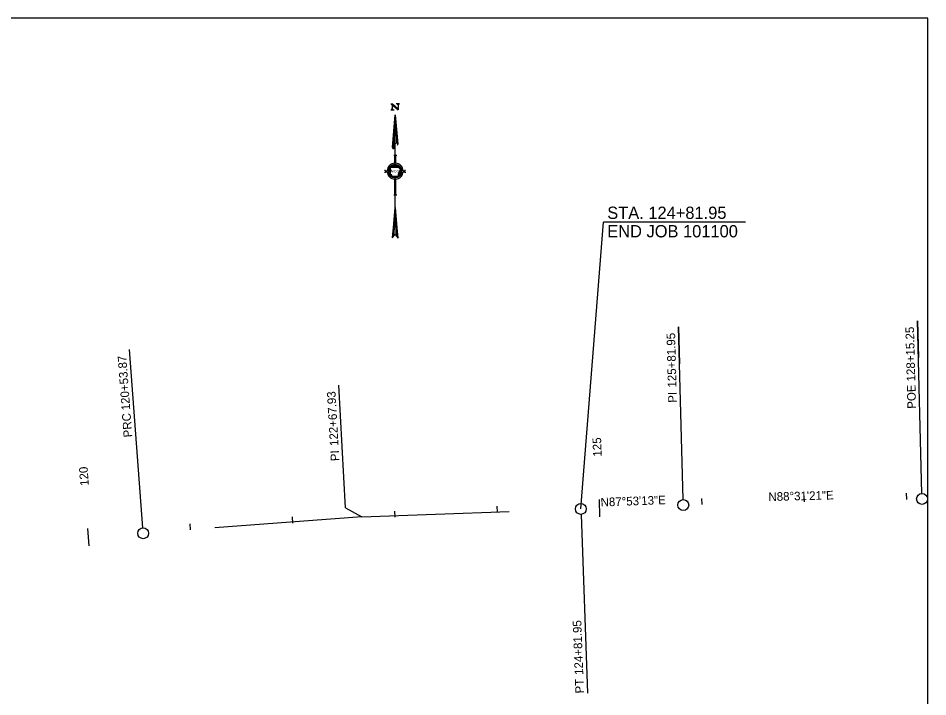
# Model space of a CAD drawing. Extents: x 1806834 to 1810084, y 678065 to 679314.
# Drawn here: x 1809196 to 1810084, y 678402 to 679065 of the extents above; entities that cross this region are included whole.
import ezdxf

# ---------------------------------------------------------------- set-up
doc = ezdxf.new("R2010")
doc.units = 0
for name, color, linetype in [('_PROJECT LIMITS', 7, 'Continuous'), ('Default', 7, 'Continuous'), ('DSN_DRFT_Guideline-No-Plot', 7, 'Continuous'), ('DSN_RDWY_Alignment Annotation', 7, 'Continuous')]:
    doc.layers.add(name, color=color, linetype=linetype)

msp = doc.modelspace()

# ---------------------------------------------------------------- linework, layer by layer
at = {"layer": '_PROJECT LIMITS'}
for p in [(1809745.12, 678585.51), (1809905.96, 678865.52)]:
    msp.add_line(p, (1809767.17, 678865.52), dxfattribs=at)
at = {"layer": 'Default'}
for p, q in [((1809559.44, 678980.98), (1809561.21, 678980.98)), ((1809559.98, 678980.98), (1809566.66, 678975.04)), ((1809560.06, 678980.98), (1809566.66, 678975.12)), ((1809560.13, 678980.98), (1809566.66, 678975.17)), ((1809560.21, 678980.98), (1809566.66, 678975.25)), ((1809560.29, 678980.98), (1809566.66, 678975.3)), ((1809560.37, 678980.98), (1809566.66, 678975.38)), ((1809560.42, 678980.98), (1809566.66, 678975.43)), ((1809560.49, 678980.98), (1809566.66, 678975.5)), ((1809560.57, 678980.98), (1809566.66, 678975.56)), ((1809560.65, 678980.98), (1809566.66, 678975.63)), ((1809560.73, 678980.98), (1809566.66, 678975.71)), ((1809560.8, 678980.98), (1809566.66, 678975.76)), ((1809560.83, 678980.98), (1809560.83, 678975.04)), ((1809560.88, 678980.98), (1809566.66, 678975.84)), ((1809560.93, 678980.98), (1809566.66, 678975.89)), ((1809561.01, 678980.98), (1809566.66, 678975.97)), ((1809561.09, 678980.98), (1809566.66, 678976.02)), ((1809561.16, 678980.98), (1809566.66, 678976.1)), ((1809561.21, 678980.98), (1809566.66, 678976.12)), ((1809566.27, 678980.98), (1809564.78, 678980.98)), ((1809568.02, 678980.98), (1809566.27, 678980.98)), ((1809566.66, 678980.98), (1809566.66, 678975.04)), ((1809559.44, 678975.04), (1809561.21, 678975.04)), ((1809561.21, 678975.04), (1809562.7, 678975.04)), ((1809563.83, 678921.99), (1809563.83, 678941.93)), ((1809561.44, 678937.53), (1809561.44, 678938.3)), ((1809561.83, 678937.22), (1809561.83, 678939.07)), ((1809562.19, 678937.15), (1809562.19, 678939.61)), ((1809562.65, 678937.15), (1809562.65, 678940.77)), ((1809562.37, 678930.7), (1809563.35, 678930.7)), ((1809563.35, 678922.94), (1809563.35, 678930.7)), ((1809564.32, 678922.97), (1809564.32, 678930.7)), ((1809564.32, 678930.7), (1809565.3, 678930.7)), ((1809554.1, 678915.67), (1809554.1, 678916.65)), ((1809554.1, 678915.67), (1809556.06, 678915.67)), ((1809554.1, 678913.72), (1809554.1, 678914.69)), ((1809554.1, 678914.69), (1809556.06, 678914.69)), ((1809557.26, 678913.54), (1809557.26, 678916.77)), ((1809557.49, 678912.77), (1809557.49, 678917.52)), ((1809557.75, 678912.25), (1809557.75, 678918.08)), ((1809557.98, 678911.84), (1809557.98, 678918.52)), ((1809558.23, 678911.46), (1809558.23, 678918.91)), ((1809558.46, 678911.1), (1809558.46, 678919.29)), ((1809558.72, 678910.86), (1809558.72, 678919.6)), ((1809558.95, 678910.58), (1809558.95, 678919.83)), ((1809559.49, 678916.18), (1809559.03, 678919.16)), ((1809559.03, 678919.16), (1809567.92, 678919.16)), ((1809559.21, 678919.16), (1809559.21, 678920.09)), ((1809559.21, 678910.33), (1809559.21, 678917.93)), ((1809559.29, 678911.69), (1809559.49, 678916.18)), ((1809559.44, 678919.16), (1809559.44, 678920.29)), ((1809559.44, 678915.64), (1809559.44, 678916.31)), ((1809559.7, 678919.16), (1809559.7, 678920.52)), ((1809559.93, 678919.16), (1809559.93, 678920.7)), ((1809560.19, 678919.16), (1809560.19, 678920.86)), ((1809560.42, 678919.16), (1809560.42, 678921.01)), ((1809560.67, 678919.16), (1809560.67, 678921.14)), ((1809560.91, 678919.16), (1809560.91, 678921.27)), ((1809561.16, 678919.16), (1809561.16, 678921.37)), ((1809561.39, 678919.16), (1809561.39, 678921.48)), ((1809561.62, 678919.16), (1809561.62, 678921.58)), ((1809561.88, 678919.16), (1809561.88, 678921.65)), ((1809562.11, 678919.16), (1809562.11, 678921.73)), ((1809562.37, 678919.16), (1809562.37, 678921.78)), ((1809562.6, 678919.16), (1809562.6, 678921.84)), ((1809562.86, 678919.16), (1809562.86, 678921.86)), ((1809563.09, 678919.16), (1809563.09, 678921.91)), ((1809563.35, 678919.16), (1809563.35, 678921.94)), ((1809563.58, 678919.16), (1809563.58, 678921.96)), ((1809563.83, 678919.16), (1809563.83, 678921.99)), ((1809564.07, 678919.16), (1809564.07, 678921.94)), ((1809564.32, 678919.16), (1809564.32, 678921.94)), ((1809564.55, 678919.16), (1809564.55, 678921.89)), ((1809564.81, 678919.16), (1809564.81, 678921.86)), ((1809565.04, 678919.16), (1809565.04, 678921.81)), ((1809565.3, 678919.16), (1809565.3, 678921.76)), ((1809565.53, 678919.16), (1809565.53, 678921.71)), ((1809565.76, 678919.16), (1809565.76, 678921.63)), ((1809566.02, 678919.16), (1809566.02, 678921.55)), ((1809566.25, 678919.16), (1809566.25, 678921.48)), ((1809566.51, 678919.16), (1809566.51, 678921.37)), ((1809566.74, 678919.16), (1809566.74, 678921.27)), ((1809566.99, 678919.16), (1809566.99, 678921.14)), ((1809567.23, 678919.16), (1809567.23, 678921.01)), ((1809567.48, 678919.16), (1809567.48, 678920.86)), ((1809567.87, 678914.36), (1809567.53, 678913.67)), ((1809567.71, 678919.16), (1809567.71, 678920.68)), ((1809568.07, 678918.37), (1809567.74, 678917.67)), ((1809567.74, 678917.67), (1809569.25, 678917.67)), ((1809568.38, 678915.1), (1809567.87, 678914.36)), ((1809567.92, 678919.16), (1809567.92, 678919.16)), ((1809567.92, 678919.16), (1809568.12, 678918.8)), ((1809567.97, 678919.11), (1809567.97, 678920.52)), ((1809567.97, 678917.67), (1809567.97, 678918.11)), ((1809567.97, 678909.84), (1809567.97, 678914.44)), ((1809568.12, 678918.8), (1809568.07, 678918.37)), ((1809568.2, 678917.7), (1809568.2, 678920.29)), ((1809568.2, 678910.04), (1809568.2, 678914.8)), ((1809568.66, 678915.9), (1809568.38, 678915.1)), ((1809568.46, 678917.7), (1809568.46, 678920.11)), ((1809568.46, 678910.25), (1809568.46, 678915.28)), ((1809568.66, 678915.9), (1809568.92, 678916.54)), ((1809568.69, 678917.7), (1809568.69, 678919.86)), ((1809568.69, 678910.5), (1809568.69, 678915.93)), ((1809569.36, 678917.08), (1809568.92, 678916.54)), ((1809568.95, 678917.67), (1809568.95, 678919.6)), ((1809568.95, 678910.76), (1809568.95, 678916.54)), ((1809569.18, 678917.67), (1809569.18, 678919.34)), ((1809569.18, 678911.07), (1809569.18, 678916.85)), ((1809569.25, 678917.67), (1809569.46, 678917.42)), ((1809569.46, 678917.42), (1809569.36, 678917.08)), ((1809569.44, 678917.49), (1809569.44, 678918.98)), ((1809569.44, 678911.4), (1809569.44, 678917.24)), ((1809569.67, 678911.76), (1809569.67, 678918.57)), ((1809569.9, 678912.23), (1809569.9, 678918.14)), ((1809570.15, 678912.79), (1809570.15, 678917.57)), ((1809570.39, 678913.61), (1809570.39, 678916.8)), ((1809571.6, 678915.67), (1809573.55, 678915.67)), ((1809571.6, 678914.69), (1809573.55, 678914.69)), ((1809573.55, 678915.67), (1809573.55, 678916.65)), ((1809573.55, 678914.69), (1809573.55, 678913.72)), ((1809559.67, 678911.46), (1809559.29, 678911.69)), ((1809559.44, 678910.12), (1809559.44, 678911.56)), ((1809560.42, 678911.46), (1809559.67, 678911.46)), ((1809559.7, 678909.91), (1809559.7, 678911.43)), ((1809559.93, 678909.71), (1809559.93, 678911.43)), ((1809560.19, 678909.58), (1809560.19, 678911.43)), ((1809560.42, 678909.86), (1809560.42, 678911.46)), ((1809566.63, 678909.86), (1809560.42, 678909.86)), ((1809560.42, 678909.4), (1809560.42, 678909.84)), ((1809560.67, 678909.27), (1809560.67, 678909.86)), ((1809560.91, 678909.14), (1809560.91, 678909.86)), ((1809561.16, 678909.04), (1809561.16, 678909.86)), ((1809561.39, 678908.94), (1809561.39, 678909.86)), ((1809561.62, 678908.84), (1809561.62, 678909.86)), ((1809561.88, 678908.76), (1809561.88, 678909.86)), ((1809562.11, 678908.68), (1809562.11, 678909.86)), ((1809562.37, 678908.63), (1809562.37, 678909.86)), ((1809562.6, 678908.55), (1809562.6, 678909.86)), ((1809562.86, 678908.53), (1809562.86, 678909.86)), ((1809563.09, 678908.5), (1809563.09, 678909.86)), ((1809563.35, 678908.45), (1809563.35, 678909.86)), ((1809563.35, 678892.14), (1809563.35, 678907.42)), ((1809563.58, 678908.42), (1809563.58, 678909.86)), ((1809563.83, 678908.42), (1809563.83, 678909.86)), ((1809563.83, 678879.67), (1809563.83, 678908.37)), ((1809564.07, 678908.42), (1809564.07, 678909.86)), ((1809564.32, 678908.45), (1809564.32, 678909.86)), ((1809564.32, 678892.14), (1809564.32, 678907.42)), ((1809564.55, 678908.48), (1809564.55, 678909.86)), ((1809564.81, 678908.5), (1809564.81, 678909.86)), ((1809565.04, 678908.55), (1809565.04, 678909.86)), ((1809565.3, 678908.6), (1809565.3, 678909.86)), ((1809565.53, 678908.66), (1809565.53, 678909.86)), ((1809565.76, 678908.73), (1809565.76, 678909.86)), ((1809566.02, 678908.78), (1809566.02, 678909.86)), ((1809566.25, 678908.89), (1809566.25, 678909.86)), ((1809566.51, 678908.99), (1809566.51, 678909.86)), ((1809566.94, 678910.5), (1809566.63, 678909.86)), ((1809566.74, 678909.09), (1809566.74, 678909.99)), ((1809566.99, 678912.74), (1809566.84, 678911.56)), ((1809566.84, 678911.56), (1809566.94, 678910.5)), ((1809567.53, 678913.67), (1809566.99, 678912.74)), ((1809566.99, 678909.22), (1809566.99, 678912.53)), ((1809567.23, 678909.35), (1809567.23, 678913.05)), ((1809567.48, 678909.5), (1809567.48, 678913.49)), ((1809567.71, 678909.66), (1809567.71, 678913.97)), ((1809562.37, 678892.14), (1809563.35, 678892.14)), ((1809564.32, 678892.14), (1809565.3, 678892.14)), ((1809563.83, 678879.67), (1809560.77, 678850.16)), ((1809566.8, 678849.93), (1809563.83, 678879.67)), ((1809560.77, 678850.16), (1809563.83, 678853.21)), ((1809563.83, 678853.21), (1809566.8, 678849.93))]:
    msp.add_line(p, q, dxfattribs=at)
for points in [[(1809567.48, 678980.98), (1809566.66, 678979.95), (1809565.86, 678980.98), (1809565.99, 678980.93), (1809567.38, 678980.93), (1809566.66, 678980.03), (1809566.02, 678980.87), (1809567.3, 678980.9), (1809566.66, 678980.13), (1809566.12, 678980.82), (1809567.17, 678980.85), (1809566.66, 678980.21), (1809566.22, 678980.77), (1809567.05, 678980.8), (1809566.66, 678980.31), (1809566.35, 678980.72), (1809566.94, 678980.75), (1809566.66, 678980.39), (1809566.45, 678980.67), (1809566.81, 678980.69), (1809566.66, 678980.46), (1809566.56, 678980.64), (1809566.71, 678980.64), (1809566.66, 678980.54), (1809566.63, 678980.62), (1809566.66, 678980.62)], [(1809559.98, 678975.04), (1809560.83, 678976.07), (1809561.6, 678975.04), (1809561.5, 678975.09), (1809560.08, 678975.09), (1809560.8, 678975.99), (1809561.47, 678975.14), (1809560.19, 678975.12), (1809560.8, 678975.89), (1809561.37, 678975.2), (1809560.29, 678975.17), (1809560.8, 678975.81), (1809561.24, 678975.25), (1809560.44, 678975.22), (1809560.83, 678975.74), (1809561.11, 678975.3), (1809560.55, 678975.27), (1809560.8, 678975.63), (1809561.01, 678975.35), (1809560.65, 678975.32), (1809560.8, 678975.56), (1809560.91, 678975.38), (1809560.75, 678975.38), (1809560.8, 678975.48), (1809560.85, 678975.4), (1809560.83, 678975.4)], [(1809561.27, 678938.15), (1809563.83, 678970.16), (1809566.4, 678941.64)], [(1809561.88, 678940.59), (1809563.83, 678970.16), (1809565.89, 678942.9)], [(1809562.42, 678941.28), (1809563.83, 678970.16), (1809565.2, 678943.06)], [(1809563.22, 678942.13), (1809563.83, 678970.16), (1809564.42, 678942.98)], [(1809561.57, 678851.99), (1809563.83, 678879.67), (1809565.99, 678851.9)], [(1809565.31, 678852.66), (1809563.83, 678879.67), (1809562.26, 678852.67)], [(1809562.94, 678853.33), (1809563.83, 678879.67), (1809564.61, 678853.42)]]:
    msp.add_lwpolyline(points, dxfattribs=at)
for start, end in [(93.60728, 176.42391), (183.61351, 266.41233), (3.57609, 86.41459), (273.59889, 356.38649)]:
    msp.add_arc((1809563.83, 678915.18), 7.79, start, end, dxfattribs=at)
for start_param, end_param in [(2.681637, 5.778782), (2.292506, 2.677814), (5.778782, 6.897374)]:
    msp.add_ellipse((1809563.83, 678939.84), major_axis=(-2.28, -2.53), ratio=0.467585, start_param=start_param, end_param=end_param, dxfattribs=at)
at = {"layer": 'DSN_DRFT_Guideline-No-Plot'}
msp.add_lwpolyline([(1808433.89, 678065.46), (1810083.89, 678065.46), (1810083.89, 679064.52), (1808433.89, 679064.52)], close=True, dxfattribs=at)
at = {"layer": 'DSN_RDWY_Alignment Annotation'}
for p, q in [((1810078.14, 678600.55), (1810073.79, 678769.16)), ((1810073.79, 678769.16), (1810074.72, 678733.17)), ((1809844.92, 678594.54), (1809840.57, 678763.14)), ((1809840.57, 678763.14), (1809841.5, 678727.15)), ((1809317.33, 678567.07), (1809304.37, 678741.25)), ((1809304.37, 678741.25), (1809304.37, 678741.25)), ((1809515.46, 678586.55), (1809508.8, 678706.36)), ((1809508.8, 678706.36), (1809508.8, 678706.36)), ((1809762.85, 678594.57), (1809763.47, 678577.78)), ((1809862.95, 678595.66), (1809863.1, 678589.66)), ((1809962.91, 678598.24), (1809963.07, 678592.24)), ((1810062.88, 678600.82), (1810063.03, 678594.82)), ((1810078.28, 678595.21), (1810078.28, 678595.21)), ((1809515.46, 678586.55), (1809531.2, 678577.62)), ((1809662.98, 678588.19), (1809663.24, 678582.2)), ((1809845.06, 678589.2), (1809845.06, 678589.2)), ((1809531.2, 678577.62), (1809387.6, 678566.94)), ((1809463.15, 678577.64), (1809463.52, 678571.65)), ((1809531.2, 678577.62), (1809675.1, 678582.93)), ((1809563.04, 678583.35), (1809563.36, 678577.36)), ((1809745.12, 678585.51), (1809745.12, 678585.51)), ((1809745.32, 678580.17), (1809751.76, 678405.63)), ((1809363.32, 678571.06), (1809363.74, 678565.07)), ((1809263.41, 678566.25), (1809264.58, 678549.49)), ((1809317.72, 678561.74), (1809317.72, 678561.74)), ((1809751.76, 678405.63), (1809751.76, 678405.63))]:
    msp.add_line(p, q, dxfattribs=at)
for centre in [(1809845.06, 678589.2), (1810078.28, 678595.21), (1809745.12, 678585.51), (1809317.72, 678561.74)]:
    msp.add_circle(centre, 5.34, dxfattribs=at)

# ---------------------------------------------------------------- texts
at = {"layer": '_PROJECT LIMITS'}
for s, p in [('STA. 124+81.95', (1809770.88, 678868.56)), ('END JOB 101100', (1809770.88, 678850.56))]:
    msp.add_text(s, height=12, rotation=360, dxfattribs=at).set_placement(p)
at = {"layer": 'Default'}
for s, height, p in [('A  DOT', 2.179, (1809559.41, 678914.08)), ('R', 1.45, (1809561.34, 678914.08))]:
    msp.add_text(s, height=height, dxfattribs=at).set_placement(p)
at = {"layer": 'DSN_RDWY_Alignment Annotation'}
for s, rotation, p in [('125+81.95', 91.47762, (1809838.49, 678704.04)), ('128+15.25', 91.47762, (1810071.72, 678710.06)), ('120+53.87', 94.25337, (1809305.16, 678682.1)), ('POE ', 91.47762, (1810072.41, 678683.35)), ('122+67.93', 93.18316, (1809508.48, 678647.16)), ('PI ', 91.47762, (1809838.87, 678689.23)), ('PRC', 94.25337, (1809307.13, 678655.66)), ('125', 92.11295, (1809765.5, 678636.64)), ('PI ', 93.18316, (1809509.31, 678632.36)), ('120', 93.98404, (1809264.7, 678608.28)), ('N87°53\'13"E', 2.11295, (1809764.52, 678587.81)), ('N88°31\'21"E', 1.47762, (1809928.35, 678593.14)), ('124+81.95', 92.11295, (1809747.49, 678423.6)), ('PT', 92.11295, (1809748.16, 678405.5))]:
    msp.add_text(s, height=8.4, rotation=rotation, dxfattribs=at).set_placement(p)

doc.saveas('drawing.dxf')
